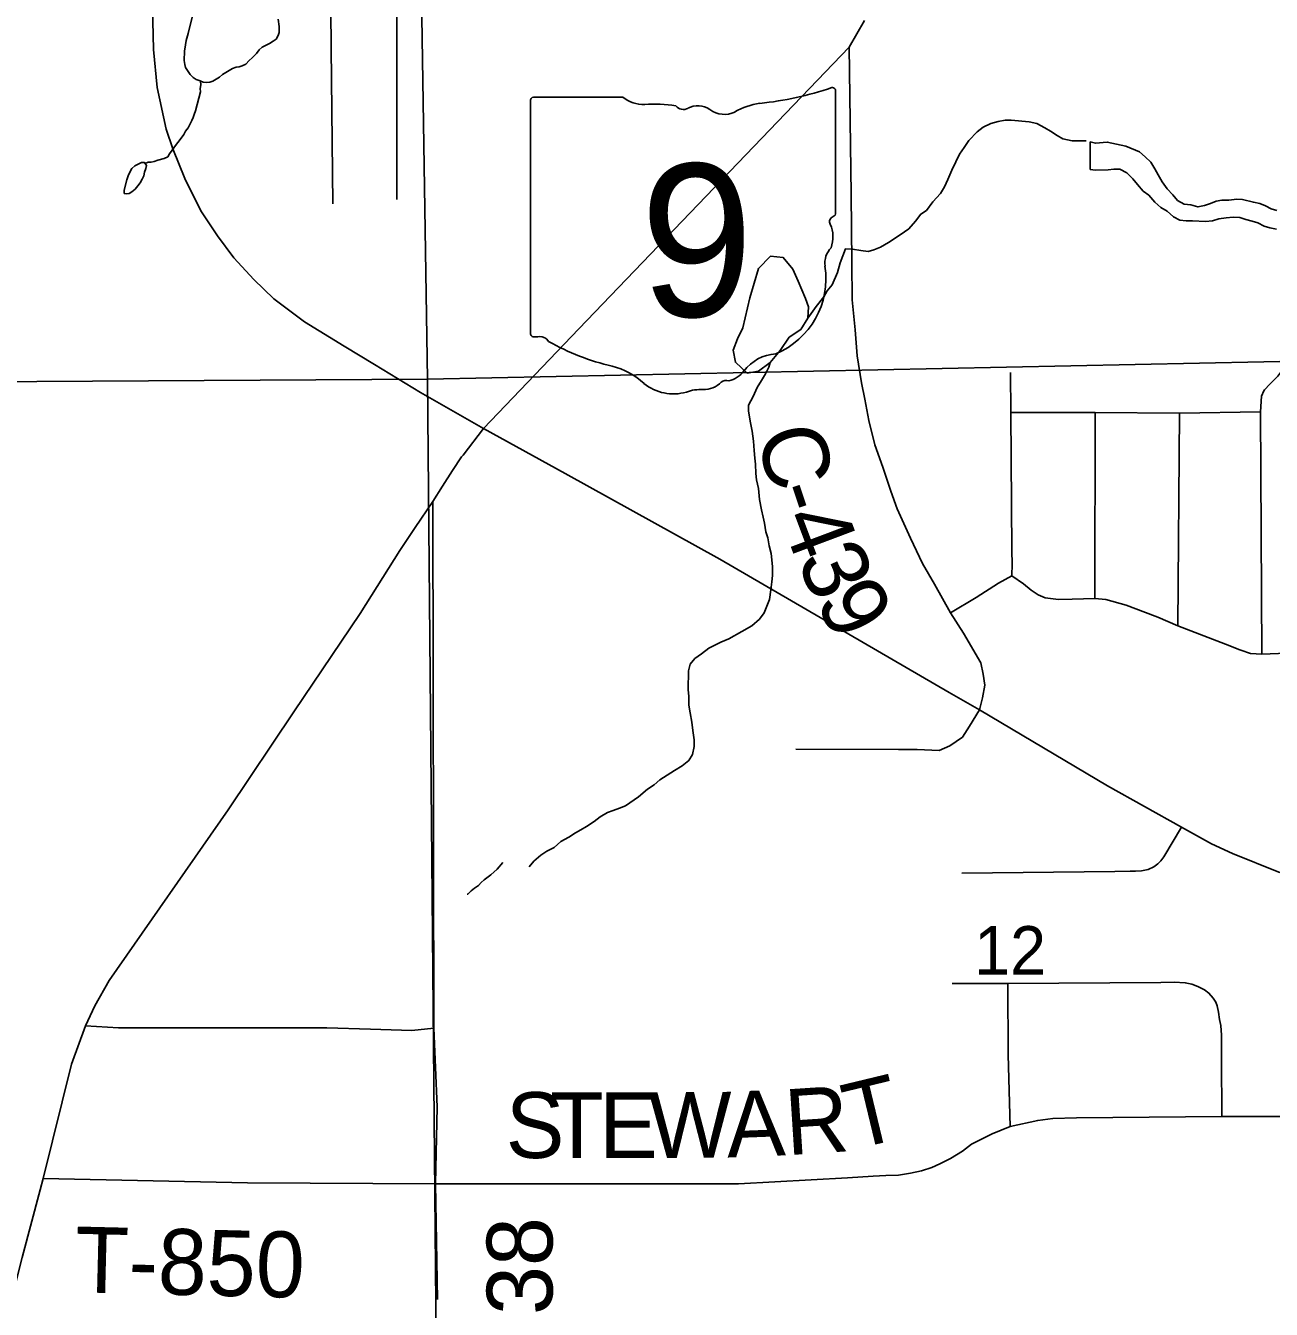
# Model space of a CAD drawing. Extents: x 0 to 34, y 0 to 22.
# Drawn here: x 4.199 to 5.275, y 15.389 to 16.498 of the extents above; entities that cross this region are included whole.
import ezdxf

# ---------------------------------------------------------------- set-up
doc = ezdxf.new("R2010")
doc.units = 0
for name, color, linetype in [('GM_X_County_Road', 7, 'Continuous'), ('GM_X_County_Road_Text', 7, 'Continuous'), ('GM_X_Minor_Lake', 7, 'Continuous'), ('GM_X_Minor_River', 7, 'Continuous'), ('GM_X_Section', 7, 'Continuous'), ('GM_X_Section_Text', 7, 'Continuous'), ('GM_X_State_Location', 7, 'Continuous'), ('GM_X_State_Route', 7, 'Continuous'), ('GM_X_State_Shield', 7, 'Continuous'), ('GM_X_Township_Road', 7, 'Continuous'), ('GM_X_Township_Road_Text', 7, 'Continuous')]:
    doc.layers.add(name, color=color, linetype=linetype)

msp = doc.modelspace()

# ---------------------------------------------------------------- linework, layer by layer
at = {"layer": 'GM_X_County_Road'}
msp.add_lwpolyline([(5.0231, 15.9069), (5.0259, 15.9174), (5.0277, 15.9283), (5.0263, 15.9378), (5.0245, 15.9476), (5.0095, 15.9731), (4.9983, 15.9907), (4.9842, 16.0155), (4.9739, 16.0332), (4.9636, 16.0551), (4.952, 16.0805), (4.9466, 16.0958), (4.9396, 16.1165), (4.9329, 16.1357), (4.9277, 16.1568), (4.9241, 16.1753), (4.9213, 16.1893), (4.9175, 16.2125), (4.9157, 16.2349), (4.9133, 16.2608), (4.9129, 16.2931), (4.9122, 16.3523), (4.9105, 16.4791)], dxfattribs=at)
at = {"layer": 'GM_X_Minor_Lake'}
for points in [[(4.3432, 16.5061), (4.3396, 16.4909), (4.3378, 16.4848), (4.3371, 16.481), (4.3364, 16.4756), (4.3364, 16.473), (4.3361, 16.4703), (4.3361, 16.4677), (4.3365, 16.4642), (4.3373, 16.4616), (4.3412, 16.4556), (4.3438, 16.4529), (4.3465, 16.4511), (4.3499, 16.45), (4.3526, 16.4489)], [(4.3526, 16.4489), (4.3556, 16.4485), (4.3583, 16.4489), (4.3609, 16.4497), (4.3666, 16.4532), (4.3692, 16.4555), (4.3749, 16.459), (4.3779, 16.4606), (4.3809, 16.4617), (4.3836, 16.4621), (4.3862, 16.4629), (4.3892, 16.4645), (4.3922, 16.4676), (4.3948, 16.4699), (4.3986, 16.4737), (4.4008, 16.4768), (4.4035, 16.4791), (4.4099, 16.4822), (4.4129, 16.4842), (4.4155, 16.4861), (4.4174, 16.4891), (4.4181, 16.4918), (4.4181, 16.4971), (4.4172, 16.5032)], [(5.1187, 16.3973), (5.1188, 16.3736)], [(5.2802, 16.3381), (5.2752, 16.3395), (5.2702, 16.342), (5.2653, 16.3442), (5.2599, 16.3452), (5.2504, 16.3477), (5.2455, 16.3479), (5.2386, 16.347), (5.2326, 16.3469), (5.2277, 16.346), (5.2228, 16.344), (5.2175, 16.3424), (5.2119, 16.3411), (5.2057, 16.3429), (5.2, 16.3435), (5.1943, 16.3468), (5.1904, 16.3516), (5.1853, 16.3568), (5.181, 16.3628), (5.1775, 16.3688), (5.1747, 16.3741), (5.1712, 16.3797), (5.1665, 16.3845), (5.1615, 16.3886), (5.1496, 16.3937), (5.1336, 16.3971), (5.1234, 16.3961), (5.1187, 16.3973)], [(5.1188, 16.3736), (5.1235, 16.3729), (5.1345, 16.3732), (5.1394, 16.3737), (5.1444, 16.3738), (5.1505, 16.3705), (5.1556, 16.3653), (5.1598, 16.3605), (5.1645, 16.3549), (5.1695, 16.3512), (5.1746, 16.3452), (5.18, 16.3408), (5.1854, 16.3375), (5.1908, 16.3326), (5.1962, 16.3297), (5.2019, 16.3291), (5.2072, 16.3292), (5.2186, 16.3287), (5.2246, 16.3292), (5.2299, 16.3309), (5.2363, 16.3318), (5.2424, 16.3323), (5.2481, 16.332), (5.2534, 16.3303), (5.2588, 16.3289), (5.2637, 16.3274), (5.2691, 16.3245), (5.2741, 16.3231), (5.2798, 16.3221)], [(4.873, 16.262), (4.8666, 16.2771), (4.8619, 16.2873), (4.8537, 16.2974), (4.8427, 16.2987), (4.8323, 16.2879), (4.8249, 16.2626)], [(4.8249, 16.2626), (4.8187, 16.2368), (4.814, 16.2272), (4.8104, 16.2176), (4.8124, 16.207), (4.8225, 16.1977), (4.8323, 16.1994), (4.8424, 16.2068), (4.851, 16.2172), (4.8588, 16.2287), (4.8689, 16.2354), (4.8748, 16.245), (4.8754, 16.2548), (4.873, 16.262)]]:
    msp.add_lwpolyline(points, dxfattribs=at)
at = {"layer": 'GM_X_Minor_River'}
for points in [[(4.3503, 16.4498), (4.3504, 16.4466), (4.35, 16.4435), (4.3501, 16.4405), (4.3457, 16.4241), (4.3446, 16.421), (4.3439, 16.4184), (4.3427, 16.4157), (4.3413, 16.413), (4.3394, 16.4096), (4.3372, 16.4065), (4.3357, 16.4038), (4.3316, 16.3981), (4.3293, 16.3954), (4.3234, 16.3869), (4.3219, 16.3843), (4.3188, 16.3831), (4.3132, 16.3815), (4.3102, 16.3803), (4.3075, 16.3799), (4.3049, 16.3799), (4.3023, 16.3787)], [(5.1154, 16.3982), (5.1101, 16.3981), (5.1033, 16.3983), (5.0953, 16.4), (5.0903, 16.4029), (5.0846, 16.4066), (5.0796, 16.4096), (5.0727, 16.4132), (5.0662, 16.4146), (5.0506, 16.4162), (5.0453, 16.416), (5.0393, 16.4148), (5.0329, 16.4131), (5.0265, 16.4099), (5.0213, 16.406), (5.0139, 16.3986), (5.0099, 16.3925), (5.0058, 16.3867), (5.0029, 16.3801), (4.9993, 16.3728), (4.996, 16.3648), (4.9931, 16.3586), (4.9895, 16.3528), (4.9828, 16.3455), (4.9773, 16.3381), (4.9724, 16.335), (4.968, 16.3288), (4.9621, 16.3222), (4.9546, 16.3171), (4.9445, 16.3104), (4.9378, 16.3065), (4.9318, 16.3041), (4.9269, 16.3028), (4.9208, 16.3034), (4.9136, 16.3048), (4.9075, 16.3051), (4.9028, 16.2928), (4.9004, 16.2844), (4.896, 16.274), (4.8916, 16.2686), (4.8887, 16.2636), (4.882, 16.2551), (4.8748, 16.245)], [(4.3034, 16.3768), (4.3018, 16.3795), (4.2992, 16.3794), (4.2935, 16.3767), (4.2909, 16.3744), (4.289, 16.3713), (4.2876, 16.368), (4.2864, 16.3645), (4.2843, 16.3557), (4.2841, 16.354), (4.2843, 16.3527)], [(4.2843, 16.3527), (4.2863, 16.3525), (4.2885, 16.3527), (4.2909, 16.3543), (4.2937, 16.3566), (4.296, 16.3593), (4.2979, 16.3619), (4.2997, 16.365), (4.3012, 16.3681), (4.3019, 16.3711), (4.303, 16.3742), (4.3034, 16.3768)], [(4.8424, 16.2068), (4.8411, 16.2028), (4.8382, 16.1971), (4.8349, 16.1913), (4.8312, 16.1851), (4.8276, 16.1774), (4.8236, 16.1701), (4.8237, 16.1652), (4.825, 16.1561), (4.8267, 16.1474), (4.828, 16.139), (4.8286, 16.1307), (4.8291, 16.1242), (4.8296, 16.1189), (4.8301, 16.1109), (4.8306, 16.1056), (4.8323, 16.0981), (4.8332, 16.0886), (4.8349, 16.0795), (4.8362, 16.0734), (4.8374, 16.0681), (4.8387, 16.0606), (4.8404, 16.0553), (4.8416, 16.0485), (4.8433, 16.042), (4.8443, 16.0306), (4.8444, 16.023), (4.8438, 16.0173), (4.8428, 16.0104), (4.8418, 16.0021), (4.8372, 15.9906), (4.8331, 15.9851), (4.8264, 15.9793), (4.8178, 15.9745), (4.8066, 15.9682), (4.7998, 15.9654), (4.7893, 15.9602), (4.783, 15.9552), (4.7774, 15.9512), (4.7733, 15.9462), (4.7719, 15.9405), (4.7715, 15.9245), (4.772, 15.9184), (4.7722, 15.9108), (4.7731, 15.9044), (4.7747, 15.8964), (4.7756, 15.8892), (4.7766, 15.8809), (4.7767, 15.8752), (4.7753, 15.8683), (4.772, 15.8633), (4.7664, 15.8586), (4.7597, 15.8546), (4.747, 15.8464)], [(4.747, 15.8464), (4.7422, 15.8421), (4.7365, 15.8385), (4.7287, 15.8319), (4.7175, 15.8241), (4.7123, 15.822), (4.7066, 15.82), (4.7017, 15.8184), (4.6954, 15.8144), (4.6902, 15.8105), (4.6838, 15.8062), (4.6789, 15.8034), (4.6741, 15.8007), (4.6685, 15.7971), (4.6614, 15.7932), (4.6558, 15.7881), (4.6494, 15.7849), (4.6442, 15.7814), (4.6382, 15.7763), (4.6342, 15.7713)], [(4.6113, 15.7751), (4.6065, 15.7694), (4.6009, 15.7644), (4.5953, 15.7601), (4.5926, 15.7578), (4.5904, 15.7551), (4.587, 15.7528), (4.584, 15.7505), (4.581, 15.7478), (4.5806, 15.7478)]]:
    msp.add_lwpolyline(points, dxfattribs=at)
at = {"layer": 'GM_X_Section'}
for points in [[(5.5401, 17.2602), (5.5468, 16.2132), (4.5462, 16.1923), (4.5299, 17.2417)], [(4.5299, 17.2417), (4.5462, 16.1923), (3.5333, 16.1865), (3.5245, 17.2236)], [(4.5462, 16.1923), (5.5468, 16.2132), (5.5538, 15.2739), (5.5548, 15.2004), (4.5552, 15.2018)], [(3.5333, 16.1865), (4.5462, 16.1923), (4.5552, 15.2018), (3.5436, 15.1965)]]:
    msp.add_lwpolyline(points, close=True, dxfattribs=at)
at = {"layer": 'GM_X_State_Route'}
for p, q in [((4.5947, 16.1499), (4.677, 16.2358)), ((4.577, 16.1269), (4.5947, 16.1499)), ((4.6651, 16.1109), (4.5947, 16.1499)), ((5.0231, 15.9069), (4.9971, 15.922))]:
    msp.add_line(p, q, dxfattribs=at)
for points in [[(4.5004, 16.2051), (4.4742, 16.221), (4.4401, 16.2418), (4.4136, 16.2617), (4.3961, 16.2786), (4.3789, 16.2971), (4.3649, 16.3161), (4.3505, 16.3379), (4.3367, 16.3657), (4.3262, 16.3912), (4.3204, 16.4083), (4.3127, 16.4444), (4.3096, 16.477), (4.3078, 16.5507), (4.3061, 16.5953)], [(4.677, 16.2358), (4.9105, 16.4791), (4.9238, 16.5022)], [(4.5947, 16.1499), (4.5401, 16.1809), (4.5004, 16.2051)], [(4.2116, 15.4924), (4.2142, 15.5021), (4.2388, 15.601), (4.2507, 15.634), (4.259, 15.6512), (4.2712, 15.6732), (4.3741, 15.8205), (4.4309, 15.9051), (4.4882, 15.9902), (4.5225, 16.0445), (4.5355, 16.0643), (4.5508, 16.0867), (4.5592, 16.1001), (4.5679, 16.1137), (4.5758, 16.1254), (4.577, 16.1269)], [(4.9971, 15.922), (4.7989, 16.0369), (4.6651, 16.1109)], [(5.1977, 15.8056), (5.1339, 15.8414), (5.0231, 15.9069)], [(5.454, 15.739), (5.429, 15.7393), (5.3887, 15.7431), (5.3518, 15.7497), (5.3077, 15.7595), (5.2818, 15.7668), (5.2418, 15.7829), (5.2236, 15.7911), (5.1977, 15.8056)], [(4.1704, 15.3381), (4.1763, 15.3542), (4.183, 15.3824), (4.1962, 15.4339), (4.2116, 15.4924)]]:
    msp.add_lwpolyline(points, dxfattribs=at)
at = {"layer": 'GM_X_State_Shield'}
for p, q in [((4.8989, 16.3362), (4.8989, 16.4409)), ((4.6352, 16.4325), (4.6352, 16.2324)), ((4.715, 16.4359), (4.6378, 16.4359)), ((4.8989, 16.3362), (4.8989, 16.3362))]:
    msp.add_line(p, q, dxfattribs=at)
for centre, radius, start, end in [((4.805, 16.7087), 0.2796, 275.8445, 288.9065), ((4.896, 16.4413), 0.00294, 351.8621, 97.738), ((4.6382, 16.4329), 0.00305, 98.1301, 188.1301), ((4.7334, 16.4591), 0.0296, 231.6195, 271.1119), ((4.7432, 16.3236), 0.1064, 80.4867, 94.9883), ((4.7674, 16.4339), 0.00855, 219.7921, 297.1024), ((4.7799, 16.4108), 0.0178, 54.4667, 119.1411), ((4.8406, 16.3748), 0.0563, 97.3462, 120.7689), ((4.8029, 16.4425), 0.0214, 233.8562, 294.8282), ((4.8982, 16.3285), 0.00454, 107.944, 210.337), ((4.8958, 16.3358), 0.00314, 289.6038, 7.7341), ((4.8693, 16.3153), 0.0273, 340.033, 23.6496), ((4.9094, 16.2924), 0.0198, 136.8065, 186.9296), ((4.8206, 16.2791), 0.0699, 292.3089, 8.9858), ((4.6383, 16.2319), 0.00308, 171.9584, 258.3066), ((4.6387, 16.2524), 0.0235, 267.339, 280.6039), ((4.6435, 16.2208), 0.00848, 29.7484, 93.2717), ((4.7506, 16.4006), 0.2019, 240.4129, 257.1985), ((4.8501, 16.1762), 0.0383, 94.4031, 142.5768), ((4.6904, 16.1424), 0.0632, 47.1842, 75.836), ((4.8016, 16.213), 0.0226, 282.8732, 323.2771), ((4.7587, 16.2198), 0.0401, 230.7004, 286.2918), ((4.7819, 16.1506), 0.0329, 85.6951, 111.2099), ((4.7848, 16.2048), 0.0214, 268.777, 315.5493), ((4.8041, 16.1854), 0.00601, 65.7517, 132.6484)]:
    msp.add_arc(centre, radius, start, end, dxfattribs=at)
at = {"layer": 'GM_X_Township_Road'}
for p, q in [((5.0503, 16.1636), (5.1232, 16.1636)), ((5.1228, 16.0031), (5.1232, 16.1636)), ((5.1232, 16.1636), (5.1961, 16.1632)), ((5.1945, 15.9794), (5.1961, 16.1632)), ((5.1961, 16.1632), (5.2661, 16.1641)), ((4.5517, 15.6319), (4.5508, 16.0867)), ((4.5548, 15.3976), (4.5531, 15.4977))]:
    msp.add_line(p, q, dxfattribs=at)
for points in [[(4.4646, 16.3439), (4.4631, 16.4782), (4.4628, 16.5114), (4.4611, 16.6886)], [(4.5198, 16.3475), (4.5198, 16.5126), (4.5198, 16.5569), (4.5185, 16.689)], [(5.2696, 16.1831), (5.2742, 16.1881), (5.2809, 16.1949), (5.2844, 16.1997), (5.2858, 16.2066)], [(4.9983, 15.9907), (5.0203, 16.004), (5.0396, 16.0162), (5.0513, 16.0227), (5.0515, 16.0331), (5.0513, 16.0443), (5.0503, 16.1636), (5.0501, 16.1981)], [(5.2672, 15.9551), (5.2661, 16.1641), (5.2668, 16.1778), (5.2689, 16.1823), (5.2696, 16.1831)], [(5.0513, 16.0227), (5.0612, 16.0157), (5.0678, 16.0103), (5.0738, 16.0063), (5.0799, 16.0036), (5.0915, 16.0021), (5.1032, 16.0024)], [(5.1032, 16.0024), (5.1228, 16.0031), (5.1323, 16.0022), (5.15, 15.9973), (5.1749, 15.9879), (5.1774, 15.9868)], [(5.1774, 15.9868), (5.1945, 15.9794), (5.2357, 15.9637), (5.2482, 15.9586)], [(5.2482, 15.9586), (5.2491, 15.9583), (5.2574, 15.9556), (5.2672, 15.9551), (5.3313, 15.9575)], [(4.8644, 15.8729), (4.9531, 15.8726), (4.9695, 15.8726), (4.9884, 15.8719), (4.9976, 15.8757), (5.0084, 15.8834), (5.0147, 15.8929), (5.0231, 15.9069)], [(5.008, 15.7659), (5.1401, 15.7674), (5.1533, 15.7677), (5.1579, 15.7677), (5.1631, 15.7678), (5.1689, 15.7689), (5.1738, 15.7712), (5.1773, 15.7739), (5.1798, 15.7764), (5.1826, 15.78), (5.1977, 15.8056)], [(4.9996, 15.6706), (5.0477, 15.6706), (5.18, 15.6715), (5.1915, 15.6717), (5.201, 15.6713), (5.2067, 15.6699), (5.212, 15.668), (5.2176, 15.665), (5.2214, 15.6623), (5.225, 15.6579), (5.2274, 15.6546), (5.2286, 15.6512), (5.2297, 15.6458), (5.2307, 15.6396), (5.2317, 15.6343), (5.2323, 15.6259), (5.2322, 15.6057), (5.2326, 15.5558)], [(5.0496, 15.5471), (5.0481, 15.609), (5.0477, 15.6706)], [(4.2507, 15.634), (4.2792, 15.6323), (4.3326, 15.6323), (4.4594, 15.6322), (4.4971, 15.6313), (4.5327, 15.6301), (4.5517, 15.6319)], [(4.5531, 15.4977), (4.5547, 15.5642), (4.5517, 15.6319)], [(4.2142, 15.5021), (4.3909, 15.4985), (4.5531, 15.4977), (4.8151, 15.4977), (4.9091, 15.5027), (4.9313, 15.5041), (4.9423, 15.5047), (4.9532, 15.5052), (4.9635, 15.5069), (4.9732, 15.5089), (4.982, 15.5117), (4.9889, 15.515), (4.9981, 15.5195), (5.0085, 15.5259), (5.0164, 15.5319), (5.0341, 15.5409), (5.0496, 15.5471), (5.0736, 15.5524), (5.0865, 15.5541), (5.107, 15.5547), (5.2326, 15.5558), (5.3838, 15.5558), (5.5556, 15.5593)]]:
    msp.add_lwpolyline(points, dxfattribs=at)

# ---------------------------------------------------------------- texts
at = {"layer": 'GM_X_County_Road_Text'}
for s, rotation, p in [('C', 284.2418, (4.8301, 16.1456)), ('-', 288.4346, (4.8428, 16.0964)), ('4', 290.5812, (4.8509, 16.0723)), ('3', 294.3378, (4.8647, 16.036)), ('9', 298.1061, (4.8808, 16.0007))]:
    msp.add_text(s, height=0.0568, rotation=rotation, dxfattribs=at).set_placement(p)
at = {"layer": 'GM_X_Section_Text'}
msp.add_text('12', height=0.04186, rotation=0, dxfattribs=at).set_placement((5.0185, 15.6783))
at = {"layer": 'GM_X_State_Location'}
for s in ['s', 'r']:
    msp.add_text(s, height=0.000189, dxfattribs=at).set_placement((4.7641, 16.3191))
msp.add_text('9', height=0.000189, rotation=0, dxfattribs=at).set_placement((4.7356, 16.3053))
at = {"layer": 'GM_X_State_Shield'}
msp.add_text('9', height=0.1318, dxfattribs=at).set_placement((4.7299, 16.2465))
at = {"layer": 'GM_X_Township_Road_Text'}
for s, height, rotation, p in [('T', 0.0568, 13.5375, (4.9141, 15.5269)), ('S', 0.0568, 0, (4.6139, 15.5199)), ('T', 0.0568, 0, (4.6522, 15.5199)), ('E', 0.0568, 0, (4.6947, 15.5199)), ('W', 0.0568, 0.3024, (4.7375, 15.5199)), ('A', 0.0568, 2.2186, (4.8055, 15.5203)), ('R', 0.0568, 3.7122, (4.857, 15.5223)), ('T-738', 0.05682, 90.0342, (4.6544, 15.2704)), ('T-850', 0.05682, 358.6034, (4.2411, 15.404))]:
    msp.add_text(s, height=height, rotation=rotation, dxfattribs=at).set_placement(p)

doc.saveas('drawing.dxf')
